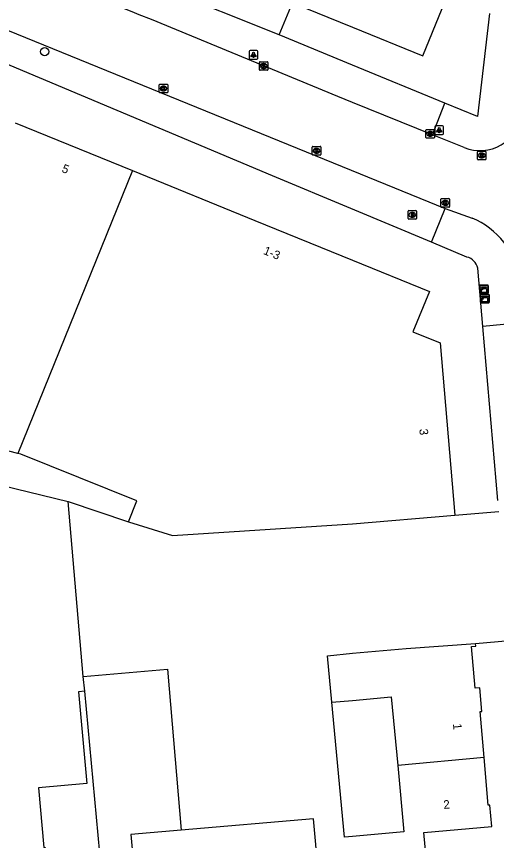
# Model space of a CAD drawing. Extents: x 160557 to 161245, y 385330 to 386505.
# Drawn here: x 160960.7 to 161016.8, y 385636 to 385732.3 of the extents above; entities that cross this region are included whole.
import ezdxf

# ---------------------------------------------------------------- set-up
doc = ezdxf.new("R2010")
doc.units = 0
for name, color, linetype in [('IMGEO_Boom', 7, 'Continuous'), ('IMGEO_Brandkraan', 7, 'Continuous'), ('IMGEO_Erf', 7, 'Continuous'), ('IMGEO_Kast', 7, 'Continuous'), ('IMGEO_Kolk', 7, 'Continuous'), ('IMGEO_Lichtpunt', 7, 'Continuous'), ('IMGEO_Pand', 7, 'Continuous'), ('IMGEO_Pand_nummerreeks', 7, 'Continuous'), ('IMGEO_Parkeervlak_open', 7, 'Continuous'), ('IMGEO_Rijbaan_lokaal_gesloten', 7, 'Continuous'), ('IMGEO_Rioolput', 7, 'Continuous'), ('IMGEO_Voetpad_open', 7, 'Continuous')]:
    doc.layers.add(name, color=color, linetype=linetype)

msp = doc.modelspace()

# ---------------------------------------------------------------- linework, layer by layer
at = {"layer": 'IMGEO_Boom'}
msp.add_circle((160964.039, 385728.203), 0.489, dxfattribs=at)
at = {"layer": 'IMGEO_Brandkraan'}
for p, q in [((161006.486, 385708.701), (161006.486, 385709.553)), ((161006.561, 385709.627), (161007.413, 385709.627)), ((161006.974, 385709.407), (161006.999, 385709.407)), ((161007.487, 385709.553), (161007.487, 385708.701)), ((161007.413, 385708.627), (161006.561, 385708.627)), ((161006.997, 385708.847), (161006.972, 385708.847))]:
    msp.add_line(p, q, dxfattribs=at)
for points in [[(161006.486, 385708.701), (161006.486, 385709.553)], [(161006.561, 385709.627), (161007.413, 385709.627)], [(161006.834, 385709.327), (161006.834, 385708.927), (161007.047, 385708.927)], [(161007.065, 385709.327), (161006.834, 385709.327)], [(161007.013, 385709.246), (161006.959, 385709.246), (161006.959, 385709.17)], [(161006.959, 385709.17), (161007.012, 385709.17)], [(161007.021, 385709.094), (161006.959, 385709.094), (161006.959, 385709.013)], [(161007.487, 385709.553), (161007.487, 385708.701)], [(161007.413, 385708.627), (161006.561, 385708.627)], [(161006.959, 385709.013), (161007.021, 385709.013)]]:
    msp.add_lwpolyline(points, dxfattribs=at)
for centre, radius, start, end in [((161006.563, 385709.551), 0.0765, 91.55205, 178.44795), ((161006.563, 385709.551), 0.0765, 91.55205, 178.44795), ((161007.014, 385709.208), 0.0379, 267.82845, 90.93552), ((161007.022, 385709.053), 0.0404, 269.87594, 90.50774), ((161007.069, 385709.182), 0.145, 59.4692, 91.53667), ((161007.094, 385709.229), 0.0922, 285.51372, 58.15012), ((161007.099, 385709.037), 0.105, 301.31148, 78.98903), ((161007.411, 385709.551), 0.0765, 1.55205, 88.44795), ((161007.411, 385709.551), 0.0765, 1.55205, 88.44795), ((161006.563, 385708.703), 0.0765, 181.55205, 268.44795), ((161006.563, 385708.703), 0.0765, 181.55205, 268.44795), ((161007.053, 385709.178), 0.251, 268.66757, 293.53466), ((161007.411, 385708.703), 0.0765, 271.55205, 358.44795), ((161007.411, 385708.703), 0.0765, 271.55205, 358.44795)]:
    msp.add_arc(centre, radius, start, end, dxfattribs=at)
for centre, major_axis, ratio, start_param, end_param in [((161006.973, 385709.127), (-0.387, 0.002), 0.722429, 4.712389, 7.853982), ((161006.998, 385709.127), (-0.39, 0.002), 0.717154, 1.570796, 4.712389)]:
    msp.add_ellipse(centre, major_axis=major_axis, ratio=ratio, start_param=start_param, end_param=end_param, dxfattribs=at)
at = {"layer": 'IMGEO_Erf'}
msp.add_lwpolyline([(160970.885, 385630.314), (160968.714, 385653.444)], dxfattribs=at)
at = {"layer": 'IMGEO_Kast'}
for p, q in [((161014.865, 385699.997), (161014.865, 385700.838)), ((161014.865, 385700.838), (161014.865, 385699.997)), ((161014.94, 385700.922), (161015.781, 385700.922)), ((161015.781, 385700.922), (161014.94, 385700.922)), ((161015.865, 385700.847), (161015.865, 385700.006)), ((161015.865, 385700.006), (161015.865, 385700.847)), ((161015.79, 385699.922), (161014.949, 385699.922)), ((161014.949, 385699.922), (161015.79, 385699.922)), ((161014.96, 385698.911), (161014.96, 385699.752)), ((161014.96, 385699.752), (161014.96, 385698.911)), ((161015.035, 385699.836), (161015.876, 385699.836)), ((161015.876, 385699.836), (161015.035, 385699.836)), ((161015.96, 385699.761), (161015.96, 385698.92)), ((161015.96, 385698.92), (161015.96, 385699.761)), ((161015.885, 385698.836), (161015.044, 385698.836)), ((161015.044, 385698.836), (161015.885, 385698.836))]:
    msp.add_line(p, q, dxfattribs=at)
for points in [[(161015.06, 385700.712), (161015.66, 385700.712), (161015.66, 385700.627), (161015.06, 385700.627), (161015.06, 385700.712)], [(161015.06, 385700.537), (161015.66, 385700.537), (161015.66, 385700.048), (161015.06, 385700.048), (161015.06, 385700.537)], [(161015.155, 385699.626), (161015.755, 385699.626), (161015.755, 385699.541), (161015.155, 385699.541), (161015.155, 385699.626)], [(161015.155, 385699.451), (161015.755, 385699.451), (161015.755, 385698.962), (161015.155, 385698.962), (161015.155, 385699.451)]]:
    msp.add_lwpolyline(points, dxfattribs=at)
for centre in [(161015.144, 385700.386), (161015.239, 385699.3)]:
    msp.add_circle(centre, 0.0377, dxfattribs=at)
for centre, start, end in [((161014.943, 385700.844), 92.4484, 184.28452), ((161014.943, 385700.844), 92.4484, 184.28452), ((161015.787, 385700.844), 2.4484, 94.28452), ((161015.787, 385700.844), 2.4484, 94.28452), ((161014.943, 385700), 182.4484, 274.28452), ((161014.943, 385700), 182.4484, 274.28452), ((161015.038, 385699.758), 92.4484, 184.28452), ((161015.038, 385699.758), 92.4484, 184.28452), ((161015.787, 385700), 272.4484, 4.28452), ((161015.787, 385700), 272.4484, 4.28452), ((161015.882, 385699.758), 2.4484, 94.28452), ((161015.882, 385699.758), 2.4484, 94.28452), ((161015.038, 385698.914), 182.4484, 274.28452), ((161015.038, 385698.914), 182.4484, 274.28452), ((161015.882, 385698.914), 272.4484, 4.28452), ((161015.882, 385698.914), 272.4484, 4.28452)]:
    msp.add_arc(centre, 0.0779, start, end, dxfattribs=at)
at = {"layer": 'IMGEO_Kolk'}
for p, q in [((160989.125, 385726.097), (160989.125, 385726.949)), ((160989.2, 385727.023), (160990.052, 385727.023)), ((160989.613, 385726.803), (160989.638, 385726.803)), ((160990.126, 385726.949), (160990.126, 385726.097)), ((160990.052, 385726.023), (160989.2, 385726.023)), ((160989.636, 385726.243), (160989.611, 385726.243)), ((160977.415, 385723.468), (160977.415, 385724.32)), ((160977.49, 385724.394), (160978.342, 385724.394)), ((160977.926, 385723.614), (160977.901, 385723.614)), ((160977.903, 385724.174), (160977.928, 385724.174)), ((160978.416, 385724.32), (160978.416, 385723.468)), ((160978.342, 385723.394), (160977.49, 385723.394)), ((161008.575, 385718.165), (161008.575, 385719.017)), ((161008.65, 385719.091), (161009.502, 385719.091)), ((161009.063, 385718.871), (161009.088, 385718.871)), ((161009.576, 385719.017), (161009.576, 385718.165)), ((161009.502, 385718.091), (161008.65, 385718.091)), ((161009.086, 385718.311), (161009.061, 385718.311)), ((160995.306, 385716.195), (160995.306, 385717.047)), ((160995.381, 385717.121), (160996.233, 385717.121)), ((160995.794, 385716.901), (160995.819, 385716.901)), ((160996.307, 385717.047), (160996.307, 385716.195)), ((160996.233, 385716.121), (160995.381, 385716.121)), ((160995.817, 385716.341), (160995.792, 385716.341)), ((161010.406, 385711.021), (161011.258, 385711.021)), ((161010.331, 385710.095), (161010.331, 385710.947)), ((161010.842, 385710.241), (161010.817, 385710.241)), ((161010.819, 385710.801), (161010.844, 385710.801)), ((161011.332, 385710.947), (161011.332, 385710.095)), ((161011.258, 385710.021), (161010.406, 385710.021))]:
    msp.add_line(p, q, dxfattribs=at)
for points in [[(160989.125, 385726.097), (160989.125, 385726.949)], [(160989.2, 385727.023), (160990.052, 385727.023)], [(160989.446, 385726.723), (160989.569, 385726.723), (160989.569, 385726.572), (160989.699, 385726.723), (160989.863, 385726.723), (160989.717, 385726.572), (160989.87, 385726.323), (160989.718, 385726.323), (160989.633, 385726.487), (160989.569, 385726.42), (160989.569, 385726.323), (160989.446, 385726.323), (160989.446, 385726.723)], [(160990.126, 385726.949), (160990.126, 385726.097)], [(160990.052, 385726.023), (160989.2, 385726.023)], [(160977.415, 385723.468), (160977.415, 385724.32)], [(160977.49, 385724.394), (160978.342, 385724.394)], [(160977.736, 385724.094), (160977.859, 385724.094), (160977.859, 385723.943), (160977.989, 385724.094), (160978.153, 385724.094), (160978.007, 385723.943), (160978.16, 385723.694), (160978.008, 385723.694), (160977.923, 385723.858), (160977.859, 385723.791), (160977.859, 385723.694), (160977.736, 385723.694), (160977.736, 385724.094)], [(160978.416, 385724.32), (160978.416, 385723.468)], [(160978.342, 385723.394), (160977.49, 385723.394)], [(161008.575, 385718.165), (161008.575, 385719.017)], [(161008.65, 385719.091), (161009.502, 385719.091)], [(161008.896, 385718.791), (161009.019, 385718.791), (161009.019, 385718.64), (161009.149, 385718.791), (161009.313, 385718.791), (161009.167, 385718.64), (161009.32, 385718.391), (161009.168, 385718.391), (161009.083, 385718.555), (161009.019, 385718.488), (161009.019, 385718.391), (161008.896, 385718.391), (161008.896, 385718.791)], [(161009.576, 385719.017), (161009.576, 385718.165)], [(161009.502, 385718.091), (161008.65, 385718.091)], [(160995.306, 385716.195), (160995.306, 385717.047)], [(160995.381, 385717.121), (160996.233, 385717.121)], [(160995.627, 385716.821), (160995.75, 385716.821), (160995.75, 385716.67), (160995.88, 385716.821), (160996.044, 385716.821), (160995.898, 385716.67), (160996.051, 385716.421), (160995.899, 385716.421), (160995.814, 385716.585), (160995.75, 385716.518), (160995.75, 385716.421), (160995.627, 385716.421), (160995.627, 385716.821)], [(160996.307, 385717.047), (160996.307, 385716.195)], [(160996.233, 385716.121), (160995.381, 385716.121)], [(161010.406, 385711.021), (161011.258, 385711.021)], [(161010.331, 385710.095), (161010.331, 385710.947)], [(161010.652, 385710.721), (161010.775, 385710.721), (161010.775, 385710.57), (161010.905, 385710.721), (161011.069, 385710.721), (161010.923, 385710.57), (161011.076, 385710.321), (161010.924, 385710.321), (161010.839, 385710.485), (161010.775, 385710.418), (161010.775, 385710.321), (161010.652, 385710.321), (161010.652, 385710.721)], [(161011.332, 385710.947), (161011.332, 385710.095)], [(161011.258, 385710.021), (161010.406, 385710.021)]]:
    msp.add_lwpolyline(points, dxfattribs=at)
for centre, start, end in [((160989.202, 385726.947), 91.55205, 178.44795), ((160989.202, 385726.947), 91.55205, 178.44795), ((160990.05, 385726.947), 1.55205, 88.44795), ((160990.05, 385726.947), 1.55205, 88.44795), ((160989.202, 385726.099), 181.55205, 268.44795), ((160989.202, 385726.099), 181.55205, 268.44795), ((160990.05, 385726.099), 271.55205, 358.44795), ((160990.05, 385726.099), 271.55205, 358.44795), ((160977.492, 385724.318), 91.55205, 178.44795), ((160977.492, 385724.318), 91.55205, 178.44795), ((160978.34, 385724.318), 1.55205, 88.44795), ((160978.34, 385724.318), 1.55205, 88.44795), ((160977.492, 385723.47), 181.55205, 268.44795), ((160977.492, 385723.47), 181.55205, 268.44795), ((160978.34, 385723.47), 271.55205, 358.44795), ((160978.34, 385723.47), 271.55205, 358.44795), ((161008.652, 385719.015), 91.55205, 178.44795), ((161008.652, 385719.015), 91.55205, 178.44795), ((161009.5, 385719.015), 1.55205, 88.44795), ((161009.5, 385719.015), 1.55205, 88.44795), ((161008.652, 385718.167), 181.55205, 268.44795), ((161008.652, 385718.167), 181.55205, 268.44795), ((161009.5, 385718.167), 271.55205, 358.44795), ((161009.5, 385718.167), 271.55205, 358.44795), ((160995.383, 385717.045), 91.55205, 178.44795), ((160995.383, 385717.045), 91.55205, 178.44795), ((160996.231, 385717.045), 1.55205, 88.44795), ((160996.231, 385717.045), 1.55205, 88.44795), ((160995.383, 385716.197), 181.55205, 268.44795), ((160995.383, 385716.197), 181.55205, 268.44795), ((160996.231, 385716.197), 271.55205, 358.44795), ((160996.231, 385716.197), 271.55205, 358.44795), ((161010.408, 385710.945), 91.55205, 178.44795), ((161010.408, 385710.945), 91.55205, 178.44795), ((161011.256, 385710.945), 1.55205, 88.44795), ((161011.256, 385710.945), 1.55205, 88.44795), ((161010.408, 385710.097), 181.55205, 268.44795), ((161010.408, 385710.097), 181.55205, 268.44795), ((161011.256, 385710.097), 271.55205, 358.44795), ((161011.256, 385710.097), 271.55205, 358.44795)]:
    msp.add_arc(centre, 0.0765, start, end, dxfattribs=at)
for centre, major_axis, ratio, start_param, end_param in [((160989.612, 385726.523), (-0.387, 0.002), 0.722429, 4.712389, 7.853982), ((160989.637, 385726.523), (-0.39, 0.002), 0.717154, 1.570796, 4.712389), ((160977.902, 385723.894), (-0.387, 0.002), 0.722429, 4.712389, 7.853982), ((160977.927, 385723.894), (-0.39, 0.002), 0.717154, 1.570796, 4.712389), ((161009.062, 385718.591), (-0.387, 0.002), 0.722429, 4.712389, 7.853982), ((161009.087, 385718.591), (-0.39, 0.002), 0.717154, 1.570796, 4.712389), ((160995.793, 385716.621), (-0.387, 0.002), 0.722429, 4.712389, 7.853982), ((160995.818, 385716.621), (-0.39, 0.002), 0.717154, 1.570796, 4.712389), ((161010.818, 385710.521), (-0.387, 0.002), 0.722429, 4.712389, 7.853982), ((161010.843, 385710.521), (-0.39, 0.002), 0.717154, 1.570796, 4.712389)]:
    msp.add_ellipse(centre, major_axis=major_axis, ratio=ratio, start_param=start_param, end_param=end_param, dxfattribs=at)
at = {"layer": 'IMGEO_Lichtpunt'}
for p, q in [((160987.935, 385728.228), (160987.935, 385727.421)), ((160987.935, 385728.228), (160987.935, 385727.421)), ((160988.837, 385728.323), (160988.029, 385728.323)), ((160988.837, 385728.323), (160988.029, 385728.323)), ((160988.931, 385727.421), (160988.931, 385728.228)), ((160988.931, 385727.421), (160988.931, 385728.228)), ((160988.029, 385727.327), (160988.837, 385727.327)), ((160988.029, 385727.327), (160988.837, 385727.327)), ((161009.626, 385719.424), (161009.626, 385718.617)), ((161009.626, 385719.424), (161009.626, 385718.617)), ((161010.528, 385719.519), (161009.72, 385719.519)), ((161010.528, 385719.519), (161009.72, 385719.519)), ((161010.622, 385718.617), (161010.622, 385719.424)), ((161010.622, 385718.617), (161010.622, 385719.424)), ((161009.72, 385718.523), (161010.528, 385718.523)), ((161009.72, 385718.523), (161010.528, 385718.523))]:
    msp.add_line(p, q, dxfattribs=at)
for points in [[(160988.309, 385727.892), (160988.348, 385727.864), (160988.16, 385727.602), (160988.122, 385727.629), (160988.309, 385727.892)], [(160988.411, 385727.844), (160988.458, 385727.844), (160988.458, 385727.522), (160988.411, 385727.522), (160988.411, 385727.844)], [(160988.521, 385727.864), (160988.559, 385727.891), (160988.746, 385727.629), (160988.707, 385727.601), (160988.521, 385727.864)], [(161010, 385719.088), (161010.039, 385719.06), (161009.851, 385718.798), (161009.813, 385718.825), (161010, 385719.088)], [(161010.102, 385719.04), (161010.149, 385719.04), (161010.149, 385718.718), (161010.102, 385718.718), (161010.102, 385719.04)], [(161010.212, 385719.06), (161010.25, 385719.087), (161010.437, 385718.825), (161010.398, 385718.797), (161010.212, 385719.06)]]:
    msp.add_lwpolyline(points, dxfattribs=at)
for centre in [(160988.434, 385728.026), (161010.125, 385719.222)]:
    msp.add_circle(centre, 0.0994, dxfattribs=at)
for centre, start, end in [((160988.029, 385728.228), 90, 180), ((160988.029, 385728.228), 90, 180), ((160988.029, 385727.421), 180, 270), ((160988.029, 385727.421), 180, 270), ((160988.837, 385728.228), 0, 90), ((160988.837, 385728.228), 0, 90), ((160988.837, 385727.421), 270, 0), ((160988.837, 385727.421), 270, 360), ((161009.72, 385719.424), 90, 180), ((161009.72, 385719.424), 90, 180), ((161010.528, 385719.424), 0, 90), ((161010.528, 385719.424), 0, 90), ((161009.72, 385718.617), 180, 270), ((161009.72, 385718.617), 180, 270), ((161010.528, 385718.617), 270, 0), ((161010.528, 385718.617), 270, 360)]:
    msp.add_arc(centre, 0.0946, start, end, dxfattribs=at)
at = {"layer": 'IMGEO_Pand'}
for points in [[(160992.987, 385733.928), (161000, 385731.062), (161008.206, 385727.709), (161013.09, 385739.659), (161016.653, 385738.203)], [(160991.446, 385730.157), (160977.766, 385735.68)], [(160991.446, 385730.157), (160992.987, 385733.928)], [(160960.586, 385719.902), (160974.303, 385714.31)], [(160974.303, 385714.31), (160960.913, 385681.247)], [(160974.303, 385714.31), (160988.598, 385708.482), (161000, 385703.843), (161008.992, 385700.184), (161007.056, 385695.467), (161010.223, 385694.167), (161011.966, 385674.019)], [(160960.913, 385681.247), (160946.512, 385684.958), (160946.173, 385684.038), (160945.896, 385684.109)], [(160973.819, 385673.241), (160974.822, 385675.709), (160961.254, 385681.159), (160960.913, 385681.247)], [(160938.493, 385657.051), (160945.182, 385680.878), (160966.78, 385675.609)], [(160966.78, 385675.609), (160973.819, 385673.241)], [(160968.546, 385655.165), (160966.78, 385675.609)], [(161011.966, 385674.019), (161017.098, 385674.461)], [(160973.819, 385673.241), (160978.968, 385671.641), (161000, 385673.001), (161011.966, 385674.019)], [(160997.589, 385652.151), (160997.08, 385657.581), (161000.001, 385657.905), (161006.255, 385658.443), (161014.375, 385659.018)], [(161015.363, 385645.719), (161014.903, 385651.059), (161015.112, 385651.077), (161014.874, 385653.838), (161014.34, 385653.789), (161013.904, 385658.675), (161014.402, 385658.719), (161014.375, 385659.018)], [(161014.375, 385659.018), (161018.356, 385659.367)], [(160968.714, 385653.444), (160968.005, 385653.367), (160968.951, 385642.66), (160963.319, 385642.172), (160963.939, 385635.17), (160964.1, 385635.164), (160964.134, 385634.743), (160949.94, 385633.511), (160949.904, 385633.932), (160950.055, 385633.931), (160949.455, 385640.834), (160949.443, 385640.975), (160942.91, 385640.389), (160941.064, 385633.675), (160941.217, 385633.639), (160941.099, 385633.233), (160933.113, 385635.47), (160934.444, 385640.29), (160938.817, 385656.14), (160938.325, 385656.372)], [(160968.546, 385655.165), (160978.378, 385656.012), (160979.998, 385637.202)], [(160968.714, 385653.444), (160968.546, 385655.165)], [(160997.589, 385652.151), (161000, 385652.377), (161004.532, 385652.803), (161005.287, 385644.773)], [(161005.287, 385644.773), (161006.014, 385637.031), (161000, 385636.465), (160999.071, 385636.378), (160997.589, 385652.151)], [(161015.363, 385645.719), (161005.287, 385644.773)], [(161008.625, 385633.571), (161008.333, 385636.953), (161016.27, 385637.637), (161016.034, 385640.146), (161015.845, 385640.13), (161015.363, 385645.719)], [(160995.973, 385632.481), (160995.452, 385638.533), (160979.998, 385637.202)], [(160979.998, 385637.202), (160974.123, 385636.696), (160974.644, 385630.643)]]:
    msp.add_lwpolyline(points, dxfattribs=at)
at = {"layer": 'IMGEO_Parkeervlak_open'}
for points in [[(161010.79, 385722.197), (161000, 385726.633), (160991.446, 385730.157)], [(161016.988, 385675.731), (161015.221, 385696.091)]]:
    msp.add_lwpolyline(points, dxfattribs=at)
at = {"layer": 'IMGEO_Rijbaan_lokaal_gesloten'}
for points in [[(161009.325, 385718.489), (161000, 385722.257), (160998.269, 385722.956), (160976.503, 385731.943), (160975.085, 385732.523), (160974.522, 385732.753), (160964.46, 385736.867), (160957.768, 385739.604), (160952.621, 385741.708), (160946.89, 385744.043), (160944.463, 385745.032), (160932.269, 385750), (160930.166, 385750.857), (160914.917, 385757.13), (160905.328, 385761.784), (160879.178, 385774.567), (160854.667, 385786.477), (160853.863, 385786.885)], [(160877.824, 385767.253), (160909.425, 385751.357), (160913.773, 385749.567), (160937.4, 385739.851), (160999.849, 385714.356), (161010.829, 385709.873)], [(161013.051, 385716.983), (161009.325, 385718.489)], [(161010.829, 385709.873), (161013.959, 385708.754)]]:
    msp.add_lwpolyline(points, dxfattribs=at)
for centre, radius, start, end in [((161014.88, 385721.512), 4.885, 248.01399, 353.50662), ((161010.373, 385700.141), 9.33, 9.33251, 67.39419)]:
    msp.add_arc(centre, radius, start, end, dxfattribs=at)
at = {"layer": 'IMGEO_Rioolput'}
for p, q in [((161014.591, 385715.65), (161014.591, 385716.502)), ((161014.666, 385716.576), (161015.518, 385716.576)), ((161015.079, 385716.356), (161015.104, 385716.356)), ((161015.592, 385716.502), (161015.592, 385715.65)), ((161015.518, 385715.576), (161014.666, 385715.576)), ((161015.102, 385715.796), (161015.077, 385715.796))]:
    msp.add_line(p, q, dxfattribs=at)
for points in [[(161014.591, 385715.65), (161014.591, 385716.502)], [(161014.666, 385716.576), (161015.518, 385716.576)], [(161015.18, 385716.274), (161014.928, 385716.276), (161014.928, 385715.876)], [(161014.928, 385715.876), (161015.052, 385715.876), (161015.052, 385716.038), (161015.063, 385716.038)], [(161015.106, 385716.195), (161015.052, 385716.195), (161015.052, 385716.114)], [(161015.052, 385716.114), (161015.104, 385716.114)], [(161015.11, 385716.009), (161015.181, 385715.876), (161015.321, 385715.876), (161015.256, 385716.002)], [(161015.592, 385716.502), (161015.592, 385715.65)], [(161015.518, 385715.576), (161014.666, 385715.576)]]:
    msp.add_lwpolyline(points, dxfattribs=at)
for centre, radius, start, end in [((161014.668, 385716.5), 0.0765, 91.55205, 178.44795), ((161014.668, 385716.5), 0.0765, 91.55205, 178.44795), ((161015.062, 385715.985), 0.0533, 26.02933, 88.69889), ((161015.088, 385716.303), 0.19, 274.7715, 282.96867), ((161015.112, 385716.099), 0.0964, 77.00612, 93.18647), ((161015.126, 385716.156), 0.0378, 276.66336, 79.67722), ((161015.179, 385716.164), 0.109, 350.36119, 89.41601), ((161015.177, 385716.164), 0.112, 277.58423, 350.98172), ((161015.161, 385715.949), 0.108, 29.51342, 73.79051), ((161015.516, 385716.5), 0.0765, 1.55205, 88.44795), ((161015.516, 385716.5), 0.0765, 1.55205, 88.44795), ((161014.668, 385715.652), 0.0765, 181.55205, 268.44795), ((161014.668, 385715.652), 0.0765, 181.55205, 268.44795), ((161015.516, 385715.652), 0.0765, 271.55205, 358.44795), ((161015.516, 385715.652), 0.0765, 271.55205, 358.44795)]:
    msp.add_arc(centre, radius, start, end, dxfattribs=at)
for centre, major_axis, ratio, start_param, end_param in [((161015.078, 385716.076), (-0.387, 0.002), 0.722429, 4.712389, 7.853982), ((161015.103, 385716.076), (-0.39, 0.002), 0.717154, 1.570796, 4.712389)]:
    msp.add_ellipse(centre, major_axis=major_axis, ratio=ratio, start_param=start_param, end_param=end_param, dxfattribs=at)
at = {"layer": 'IMGEO_Voetpad_open'}
for points in [[(161016.005, 385732.678), (161014.591, 385720.634), (161010.79, 385722.197)], [(161009.232, 385705.924), (160999.817, 385709.872), (160990.673, 385713.706), (160950.143, 385730.7)], [(161009.325, 385718.489), (161010.79, 385722.197)], [(161009.232, 385705.924), (161010.829, 385709.873)], [(161013.354, 385704.196), (161009.232, 385705.924)], [(161015.221, 385696.091), (161014.63, 385702.902)], [(161020.042, 385696.529), (161015.221, 385696.091)]]:
    msp.add_lwpolyline(points, dxfattribs=at)
msp.add_arc((161012.959, 385702.531), 1.712, 12.5342, 76.66323, dxfattribs=at)

# ---------------------------------------------------------------- texts
at = {"layer": 'IMGEO_Pand_nummerreeks'}
for s, rotation, p in [('5', 337.81967, (160965.952, 385714.173)), ('1-3', 337.84385, (160989.507, 385704.577)), ('3', 274.94434, (161007.803, 385684.085)), ('1', 274.92441, (161011.733, 385649.648)), ('2', 4.9255, (161010.662, 385639.683))]:
    msp.add_text(s, height=1, rotation=rotation, dxfattribs=at).set_placement(p)

doc.saveas('drawing.dxf')
